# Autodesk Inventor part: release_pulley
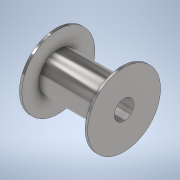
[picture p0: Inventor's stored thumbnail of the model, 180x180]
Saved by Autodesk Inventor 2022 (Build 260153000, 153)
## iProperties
Created: 2021-06
Part Number: release_pulley
Material: Stainless Steel
Document SubType Name: Modeling
Designer: Chimms
Density: 8 g/cm^3
Appearance: Weld - Stainless Steel
Author: Chimms
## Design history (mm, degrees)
sketch "Sketch1"
  geometry: C1 r 7.5 at (0, 0); 1 further point
  constraints: 1 centre point, 1 coincident
  dimensions: "d0" = 15 diameter of C1
extrude "Extrusion1" new body sketch "Sketch1" distance "d1" = 0.5; taper "d2" = 0 deg
sketch "Sketch2"
  geometry: C1 r 2 at (0, 0); C2 r 4 at (0, 0); 1 further point
  constraints: 2 centre point, 2 coincident
  dimensions: "d3" = 4 diameter of C1; "d4" = 8 diameter of C2
extrude "Extrusion2" join sketch "Sketch2" distance "d5" = 13; taper "d6" = 0 deg
sketch "Sketch3"
  geometry: C1 r 7.5 at (0, 0); 1 further point
  constraints: 1 centre point, 1 coincident
extrude "Extrusion3" join sketch "Sketch3" distance "d7" = 0.5; taper "d8" = 0 deg
sketch "Sketch4"
  geometry: C1 r 2 at (0, 0); 1 further point
  constraints: 1 centre point, 1 coincident
extrude "Extrusion4" cut sketch "Sketch4" extent not by distance; stored distance "d9" = 0; taper "d10" = 0 deg
body "Solid1"
